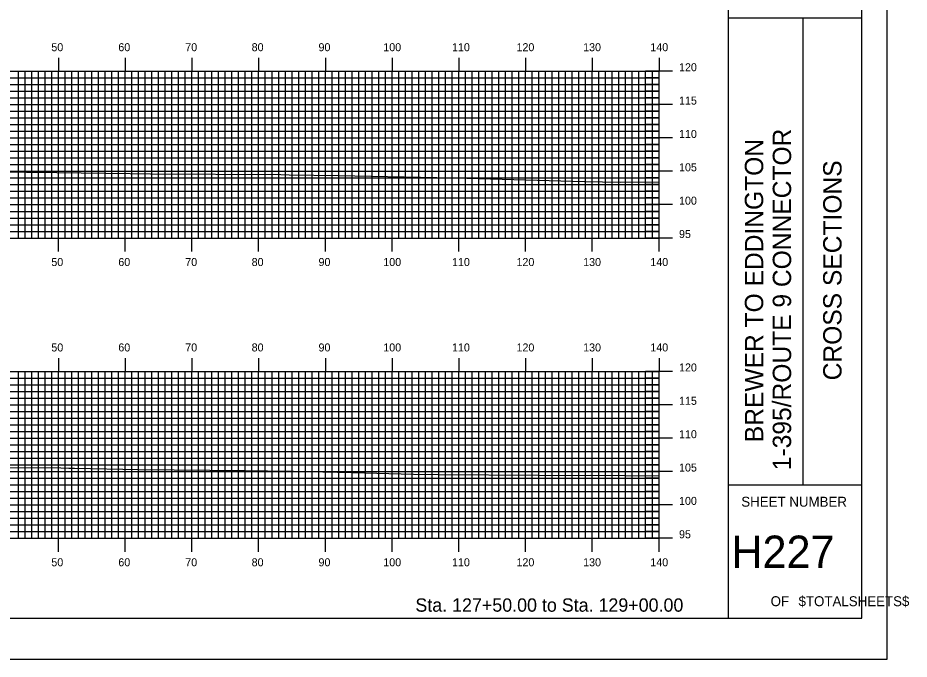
# Model space of a CAD drawing. Extents: x 1773596 to 1773940, y 442591 to 442811.
# Drawn here: x 1773806.1 to 1773939.6, y 442590.5 to 442686.7 of the extents above; entities that cross this region are included whole.
import ezdxf

# ---------------------------------------------------------------- set-up
doc = ezdxf.new("R2010")
doc.units = 0
for name, color, linetype in [('BORDER', 7, 'Continuous'), ('H_V ANNOTATION', 7, 'Continuous'), ('MAJOR', 7, 'Continuous'), ('MINOR', 7, 'Continuous'), ('PLOT BOUNDARY', 7, 'Continuous'), ('S_Roadway_Centerline', 7, 'Continuous')]:
    doc.layers.add(name, color=color, linetype=linetype)

msp = doc.modelspace()

# ---------------------------------------------------------------- linework, layer by layer
at = {"layer": 'BORDER'}
for p, q in [((1773912.55, 442596.67), (1773912.55, 442806.67)), ((1773912.55, 442686.67), (1773932.55, 442686.67)), ((1773923.73, 442616.67), (1773923.73, 442686.67)), ((1773912.55, 442616.67), (1773932.55, 442616.67))]:
    msp.add_line(p, q, dxfattribs=at)
msp.add_lwpolyline([(1773612.55, 442596.67), (1773932.55, 442596.67), (1773932.55, 442806.67), (1773612.55, 442806.67)], close=True, dxfattribs=at)
at = {"layer": 'MAJOR'}
for p, q in [((1773812.15, 442680.67), (1773812.15, 442678.67)), ((1773822.15, 442680.67), (1773822.15, 442678.67)), ((1773832.15, 442680.67), (1773832.15, 442678.67)), ((1773842.15, 442680.67), (1773842.15, 442678.67)), ((1773852.15, 442680.67), (1773852.15, 442678.67)), ((1773862.15, 442680.67), (1773862.15, 442678.67)), ((1773872.15, 442680.67), (1773872.15, 442678.67)), ((1773882.15, 442680.67), (1773882.15, 442678.67)), ((1773892.15, 442680.67), (1773892.15, 442678.67)), ((1773902.15, 442680.67), (1773902.15, 442678.67)), ((1773622.15, 442678.67), (1773902.15, 442678.67)), ((1773622.15, 442678.67), (1773902.15, 442678.67)), ((1773812.15, 442653.67), (1773812.15, 442678.67)), ((1773822.15, 442653.67), (1773822.15, 442678.67)), ((1773832.15, 442653.67), (1773832.15, 442678.67)), ((1773842.15, 442653.67), (1773842.15, 442678.67)), ((1773852.15, 442653.67), (1773852.15, 442678.67)), ((1773862.15, 442653.67), (1773862.15, 442678.67)), ((1773872.15, 442653.67), (1773872.15, 442678.67)), ((1773882.15, 442653.67), (1773882.15, 442678.67)), ((1773892.15, 442653.67), (1773892.15, 442678.67)), ((1773904.15, 442678.67), (1773900.14, 442678.67)), ((1773902.15, 442653.67), (1773902.15, 442678.67)), ((1773902.15, 442653.67), (1773902.15, 442678.67)), ((1773622.15, 442673.67), (1773902.15, 442673.67)), ((1773904.15, 442673.67), (1773900.14, 442673.67)), ((1773622.15, 442668.67), (1773902.15, 442668.67)), ((1773904.15, 442668.67), (1773900.14, 442668.67)), ((1773622.15, 442663.67), (1773902.15, 442663.67)), ((1773904.15, 442663.67), (1773900.14, 442663.67)), ((1773622.15, 442658.67), (1773902.15, 442658.67)), ((1773904.15, 442658.67), (1773900.14, 442658.67)), ((1773622.15, 442653.67), (1773902.15, 442653.67)), ((1773622.15, 442653.67), (1773902.15, 442653.67)), ((1773812.15, 442651.66), (1773812.15, 442653.67)), ((1773822.15, 442651.66), (1773822.15, 442653.67)), ((1773832.15, 442651.66), (1773832.15, 442653.67)), ((1773842.15, 442651.66), (1773842.15, 442653.67)), ((1773852.15, 442651.66), (1773852.15, 442653.67)), ((1773862.15, 442651.66), (1773862.15, 442653.67)), ((1773872.15, 442651.66), (1773872.15, 442653.67)), ((1773882.15, 442651.66), (1773882.15, 442653.67)), ((1773892.15, 442651.66), (1773892.15, 442653.67)), ((1773904.15, 442653.67), (1773900.14, 442653.67)), ((1773902.15, 442651.66), (1773902.15, 442653.67)), ((1773812.15, 442635.67), (1773812.15, 442633.67)), ((1773822.15, 442635.67), (1773822.15, 442633.67)), ((1773832.15, 442635.67), (1773832.15, 442633.67)), ((1773842.15, 442635.67), (1773842.15, 442633.67)), ((1773852.15, 442635.67), (1773852.15, 442633.67)), ((1773862.15, 442635.67), (1773862.15, 442633.67)), ((1773872.15, 442635.67), (1773872.15, 442633.67)), ((1773882.15, 442635.67), (1773882.15, 442633.67)), ((1773892.15, 442635.67), (1773892.15, 442633.67)), ((1773902.15, 442635.67), (1773902.15, 442633.67)), ((1773622.15, 442633.67), (1773902.15, 442633.67)), ((1773622.15, 442633.67), (1773902.15, 442633.67)), ((1773812.15, 442608.67), (1773812.15, 442633.67)), ((1773822.15, 442608.67), (1773822.15, 442633.67)), ((1773832.15, 442608.67), (1773832.15, 442633.67)), ((1773842.15, 442608.67), (1773842.15, 442633.67)), ((1773852.15, 442608.67), (1773852.15, 442633.67)), ((1773862.15, 442608.67), (1773862.15, 442633.67)), ((1773872.15, 442608.67), (1773872.15, 442633.67)), ((1773882.15, 442608.67), (1773882.15, 442633.67)), ((1773892.15, 442608.67), (1773892.15, 442633.67)), ((1773904.15, 442633.67), (1773900.14, 442633.67)), ((1773902.15, 442608.67), (1773902.15, 442633.67)), ((1773902.15, 442608.67), (1773902.15, 442633.67)), ((1773622.15, 442628.67), (1773902.15, 442628.67)), ((1773904.15, 442628.67), (1773900.14, 442628.67)), ((1773622.15, 442623.67), (1773902.15, 442623.67)), ((1773904.15, 442623.67), (1773900.14, 442623.67)), ((1773622.15, 442618.67), (1773902.15, 442618.67)), ((1773904.15, 442618.67), (1773900.14, 442618.67)), ((1773622.15, 442613.67), (1773902.15, 442613.67)), ((1773904.15, 442613.67), (1773900.14, 442613.67)), ((1773622.15, 442608.67), (1773902.15, 442608.67)), ((1773622.15, 442608.67), (1773902.15, 442608.67)), ((1773812.15, 442606.66), (1773812.15, 442608.67)), ((1773822.15, 442606.66), (1773822.15, 442608.67)), ((1773832.15, 442606.66), (1773832.15, 442608.67)), ((1773842.15, 442606.66), (1773842.15, 442608.67)), ((1773852.15, 442606.66), (1773852.15, 442608.67)), ((1773862.15, 442606.66), (1773862.15, 442608.67)), ((1773872.15, 442606.66), (1773872.15, 442608.67)), ((1773882.15, 442606.66), (1773882.15, 442608.67)), ((1773892.15, 442606.66), (1773892.15, 442608.67)), ((1773904.15, 442608.67), (1773900.14, 442608.67)), ((1773902.15, 442606.66), (1773902.15, 442608.67))]:
    msp.add_line(p, q, dxfattribs=at)
at = {"layer": 'MINOR'}
for p, q in [((1773806.15, 442653.67), (1773806.15, 442678.67)), ((1773807.15, 442653.67), (1773807.15, 442678.67)), ((1773808.15, 442653.67), (1773808.15, 442678.67)), ((1773809.15, 442653.67), (1773809.15, 442678.67)), ((1773810.15, 442653.67), (1773810.15, 442678.67)), ((1773811.15, 442653.67), (1773811.15, 442678.67)), ((1773813.15, 442653.67), (1773813.15, 442678.67)), ((1773814.15, 442653.67), (1773814.15, 442678.67)), ((1773815.15, 442653.67), (1773815.15, 442678.67)), ((1773816.15, 442653.67), (1773816.15, 442678.67)), ((1773817.15, 442653.67), (1773817.15, 442678.67)), ((1773818.15, 442653.67), (1773818.15, 442678.67)), ((1773819.15, 442653.67), (1773819.15, 442678.67)), ((1773820.15, 442653.67), (1773820.15, 442678.67)), ((1773821.15, 442653.67), (1773821.15, 442678.67)), ((1773823.15, 442653.67), (1773823.15, 442678.67)), ((1773824.15, 442653.67), (1773824.15, 442678.67)), ((1773825.15, 442653.67), (1773825.15, 442678.67)), ((1773826.15, 442653.67), (1773826.15, 442678.67)), ((1773827.15, 442653.67), (1773827.15, 442678.67)), ((1773828.15, 442653.67), (1773828.15, 442678.67)), ((1773829.15, 442653.67), (1773829.15, 442678.67)), ((1773830.15, 442653.67), (1773830.15, 442678.67)), ((1773831.15, 442653.67), (1773831.15, 442678.67)), ((1773833.15, 442653.67), (1773833.15, 442678.67)), ((1773834.15, 442653.67), (1773834.15, 442678.67)), ((1773835.15, 442653.67), (1773835.15, 442678.67)), ((1773836.15, 442653.67), (1773836.15, 442678.67)), ((1773837.15, 442653.67), (1773837.15, 442678.67)), ((1773838.15, 442653.67), (1773838.15, 442678.67)), ((1773839.15, 442653.67), (1773839.15, 442678.67)), ((1773840.15, 442653.67), (1773840.15, 442678.67)), ((1773841.15, 442653.67), (1773841.15, 442678.67)), ((1773843.15, 442653.67), (1773843.15, 442678.67)), ((1773844.15, 442653.67), (1773844.15, 442678.67)), ((1773845.15, 442653.67), (1773845.15, 442678.67)), ((1773846.15, 442653.67), (1773846.15, 442678.67)), ((1773847.15, 442653.67), (1773847.15, 442678.67)), ((1773848.15, 442653.67), (1773848.15, 442678.67)), ((1773849.15, 442653.67), (1773849.15, 442678.67)), ((1773850.15, 442653.67), (1773850.15, 442678.67)), ((1773851.15, 442653.67), (1773851.15, 442678.67)), ((1773853.15, 442653.67), (1773853.15, 442678.67)), ((1773854.15, 442653.67), (1773854.15, 442678.67)), ((1773855.15, 442653.67), (1773855.15, 442678.67)), ((1773856.15, 442653.67), (1773856.15, 442678.67)), ((1773857.15, 442653.67), (1773857.15, 442678.67)), ((1773858.15, 442653.67), (1773858.15, 442678.67)), ((1773859.15, 442653.67), (1773859.15, 442678.67)), ((1773860.15, 442653.67), (1773860.15, 442678.67)), ((1773861.15, 442653.67), (1773861.15, 442678.67)), ((1773863.15, 442653.67), (1773863.15, 442678.67)), ((1773864.15, 442653.67), (1773864.15, 442678.67)), ((1773865.15, 442653.67), (1773865.15, 442678.67)), ((1773866.15, 442653.67), (1773866.15, 442678.67)), ((1773867.15, 442653.67), (1773867.15, 442678.67)), ((1773868.15, 442653.67), (1773868.15, 442678.67)), ((1773869.15, 442653.67), (1773869.15, 442678.67)), ((1773870.15, 442653.67), (1773870.15, 442678.67)), ((1773871.15, 442653.67), (1773871.15, 442678.67)), ((1773873.15, 442653.67), (1773873.15, 442678.67)), ((1773874.15, 442653.67), (1773874.15, 442678.67)), ((1773875.15, 442653.67), (1773875.15, 442678.67)), ((1773876.15, 442653.67), (1773876.15, 442678.67)), ((1773877.15, 442653.67), (1773877.15, 442678.67)), ((1773878.15, 442653.67), (1773878.15, 442678.67)), ((1773879.15, 442653.67), (1773879.15, 442678.67)), ((1773880.15, 442653.67), (1773880.15, 442678.67)), ((1773881.15, 442653.67), (1773881.15, 442678.67)), ((1773883.15, 442653.67), (1773883.15, 442678.67)), ((1773884.15, 442653.67), (1773884.15, 442678.67)), ((1773885.15, 442653.67), (1773885.15, 442678.67)), ((1773886.15, 442653.67), (1773886.15, 442678.67)), ((1773887.15, 442653.67), (1773887.15, 442678.67)), ((1773888.15, 442653.67), (1773888.15, 442678.67)), ((1773889.15, 442653.67), (1773889.15, 442678.67)), ((1773890.15, 442653.67), (1773890.15, 442678.67)), ((1773891.15, 442653.67), (1773891.15, 442678.67)), ((1773893.15, 442653.67), (1773893.15, 442678.67)), ((1773894.15, 442653.67), (1773894.15, 442678.67)), ((1773895.15, 442653.67), (1773895.15, 442678.67)), ((1773896.15, 442653.67), (1773896.15, 442678.67)), ((1773897.15, 442653.67), (1773897.15, 442678.67)), ((1773898.15, 442653.67), (1773898.15, 442678.67)), ((1773899.15, 442653.67), (1773899.15, 442678.67)), ((1773900.15, 442653.67), (1773900.15, 442678.67)), ((1773901.15, 442653.67), (1773901.15, 442678.67)), ((1773622.15, 442677.67), (1773902.15, 442677.67)), ((1773902.15, 442677.67), (1773900.14, 442677.67)), ((1773622.15, 442676.67), (1773902.15, 442676.67)), ((1773622.15, 442675.67), (1773902.15, 442675.67)), ((1773902.15, 442676.67), (1773900.14, 442676.67)), ((1773902.15, 442675.67), (1773900.14, 442675.67)), ((1773622.15, 442674.67), (1773902.15, 442674.67)), ((1773902.15, 442674.67), (1773900.14, 442674.67)), ((1773622.15, 442672.67), (1773902.15, 442672.67)), ((1773622.15, 442671.67), (1773902.15, 442671.67)), ((1773902.15, 442672.67), (1773900.14, 442672.67)), ((1773902.15, 442671.67), (1773900.14, 442671.67)), ((1773622.15, 442670.67), (1773902.15, 442670.67)), ((1773902.15, 442670.67), (1773900.14, 442670.67)), ((1773622.15, 442669.67), (1773902.15, 442669.67)), ((1773902.15, 442669.67), (1773900.14, 442669.67)), ((1773622.15, 442667.67), (1773902.15, 442667.67)), ((1773902.15, 442667.67), (1773900.14, 442667.67)), ((1773622.15, 442666.67), (1773902.15, 442666.67)), ((1773902.15, 442666.67), (1773900.14, 442666.67)), ((1773622.15, 442665.67), (1773902.15, 442665.67)), ((1773902.15, 442665.67), (1773900.14, 442665.67)), ((1773622.15, 442664.67), (1773902.15, 442664.67)), ((1773902.15, 442664.67), (1773900.14, 442664.67)), ((1773622.15, 442662.67), (1773902.15, 442662.67)), ((1773902.15, 442662.67), (1773900.14, 442662.67)), ((1773622.15, 442661.67), (1773902.15, 442661.67)), ((1773902.15, 442661.67), (1773900.14, 442661.67)), ((1773622.15, 442660.67), (1773902.15, 442660.67)), ((1773622.15, 442659.67), (1773902.15, 442659.67)), ((1773902.15, 442660.67), (1773900.14, 442660.67)), ((1773902.15, 442659.67), (1773900.14, 442659.67)), ((1773622.15, 442657.67), (1773902.15, 442657.67)), ((1773902.15, 442657.67), (1773900.14, 442657.67)), ((1773622.15, 442656.67), (1773902.15, 442656.67)), ((1773622.15, 442655.67), (1773902.15, 442655.67)), ((1773902.15, 442656.67), (1773900.14, 442656.67)), ((1773902.15, 442655.67), (1773900.14, 442655.67)), ((1773622.15, 442654.67), (1773902.15, 442654.67)), ((1773902.15, 442654.67), (1773900.14, 442654.67)), ((1773806.15, 442608.67), (1773806.15, 442633.67)), ((1773807.15, 442608.67), (1773807.15, 442633.67)), ((1773808.15, 442608.67), (1773808.15, 442633.67)), ((1773809.15, 442608.67), (1773809.15, 442633.67)), ((1773810.15, 442608.67), (1773810.15, 442633.67)), ((1773811.15, 442608.67), (1773811.15, 442633.67)), ((1773813.15, 442608.67), (1773813.15, 442633.67)), ((1773814.15, 442608.67), (1773814.15, 442633.67)), ((1773815.15, 442608.67), (1773815.15, 442633.67)), ((1773816.15, 442608.67), (1773816.15, 442633.67)), ((1773817.15, 442608.67), (1773817.15, 442633.67)), ((1773818.15, 442608.67), (1773818.15, 442633.67)), ((1773819.15, 442608.67), (1773819.15, 442633.67)), ((1773820.15, 442608.67), (1773820.15, 442633.67)), ((1773821.15, 442608.67), (1773821.15, 442633.67)), ((1773823.15, 442608.67), (1773823.15, 442633.67)), ((1773824.15, 442608.67), (1773824.15, 442633.67)), ((1773825.15, 442608.67), (1773825.15, 442633.67)), ((1773826.15, 442608.67), (1773826.15, 442633.67)), ((1773827.15, 442608.67), (1773827.15, 442633.67)), ((1773828.15, 442608.67), (1773828.15, 442633.67)), ((1773829.15, 442608.67), (1773829.15, 442633.67)), ((1773830.15, 442608.67), (1773830.15, 442633.67)), ((1773831.15, 442608.67), (1773831.15, 442633.67)), ((1773833.15, 442608.67), (1773833.15, 442633.67)), ((1773834.15, 442608.67), (1773834.15, 442633.67)), ((1773835.15, 442608.67), (1773835.15, 442633.67)), ((1773836.15, 442608.67), (1773836.15, 442633.67)), ((1773837.15, 442608.67), (1773837.15, 442633.67)), ((1773838.15, 442608.67), (1773838.15, 442633.67)), ((1773839.15, 442608.67), (1773839.15, 442633.67)), ((1773840.15, 442608.67), (1773840.15, 442633.67)), ((1773841.15, 442608.67), (1773841.15, 442633.67)), ((1773843.15, 442608.67), (1773843.15, 442633.67)), ((1773844.15, 442608.67), (1773844.15, 442633.67)), ((1773845.15, 442608.67), (1773845.15, 442633.67)), ((1773846.15, 442608.67), (1773846.15, 442633.67)), ((1773847.15, 442608.67), (1773847.15, 442633.67)), ((1773848.15, 442608.67), (1773848.15, 442633.67)), ((1773849.15, 442608.67), (1773849.15, 442633.67)), ((1773850.15, 442608.67), (1773850.15, 442633.67)), ((1773851.15, 442608.67), (1773851.15, 442633.67)), ((1773853.15, 442608.67), (1773853.15, 442633.67)), ((1773854.15, 442608.67), (1773854.15, 442633.67)), ((1773855.15, 442608.67), (1773855.15, 442633.67)), ((1773856.15, 442608.67), (1773856.15, 442633.67)), ((1773857.15, 442608.67), (1773857.15, 442633.67)), ((1773858.15, 442608.67), (1773858.15, 442633.67)), ((1773859.15, 442608.67), (1773859.15, 442633.67)), ((1773860.15, 442608.67), (1773860.15, 442633.67)), ((1773861.15, 442608.67), (1773861.15, 442633.67)), ((1773863.15, 442608.67), (1773863.15, 442633.67)), ((1773864.15, 442608.67), (1773864.15, 442633.67)), ((1773865.15, 442608.67), (1773865.15, 442633.67)), ((1773866.15, 442608.67), (1773866.15, 442633.67)), ((1773867.15, 442608.67), (1773867.15, 442633.67)), ((1773868.15, 442608.67), (1773868.15, 442633.67)), ((1773869.15, 442608.67), (1773869.15, 442633.67)), ((1773870.15, 442608.67), (1773870.15, 442633.67)), ((1773871.15, 442608.67), (1773871.15, 442633.67)), ((1773873.15, 442608.67), (1773873.15, 442633.67)), ((1773874.15, 442608.67), (1773874.15, 442633.67)), ((1773875.15, 442608.67), (1773875.15, 442633.67)), ((1773876.15, 442608.67), (1773876.15, 442633.67)), ((1773877.15, 442608.67), (1773877.15, 442633.67)), ((1773878.15, 442608.67), (1773878.15, 442633.67)), ((1773879.15, 442608.67), (1773879.15, 442633.67)), ((1773880.15, 442608.67), (1773880.15, 442633.67)), ((1773881.15, 442608.67), (1773881.15, 442633.67)), ((1773883.15, 442608.67), (1773883.15, 442633.67)), ((1773884.15, 442608.67), (1773884.15, 442633.67)), ((1773885.15, 442608.67), (1773885.15, 442633.67)), ((1773886.15, 442608.67), (1773886.15, 442633.67)), ((1773887.15, 442608.67), (1773887.15, 442633.67)), ((1773888.15, 442608.67), (1773888.15, 442633.67)), ((1773889.15, 442608.67), (1773889.15, 442633.67)), ((1773890.15, 442608.67), (1773890.15, 442633.67)), ((1773891.15, 442608.67), (1773891.15, 442633.67)), ((1773893.15, 442608.67), (1773893.15, 442633.67)), ((1773894.15, 442608.67), (1773894.15, 442633.67)), ((1773895.15, 442608.67), (1773895.15, 442633.67)), ((1773896.15, 442608.67), (1773896.15, 442633.67)), ((1773897.15, 442608.67), (1773897.15, 442633.67)), ((1773898.15, 442608.67), (1773898.15, 442633.67)), ((1773899.15, 442608.67), (1773899.15, 442633.67)), ((1773900.15, 442608.67), (1773900.15, 442633.67)), ((1773901.15, 442608.67), (1773901.15, 442633.67)), ((1773622.15, 442632.67), (1773902.15, 442632.67)), ((1773622.15, 442631.67), (1773902.15, 442631.67)), ((1773902.15, 442632.67), (1773900.14, 442632.67)), ((1773902.15, 442631.67), (1773900.14, 442631.67)), ((1773622.15, 442630.67), (1773902.15, 442630.67)), ((1773902.15, 442630.67), (1773900.14, 442630.67)), ((1773622.15, 442629.67), (1773902.15, 442629.67)), ((1773902.15, 442629.67), (1773900.14, 442629.67)), ((1773622.15, 442627.67), (1773902.15, 442627.67)), ((1773902.15, 442627.67), (1773900.14, 442627.67)), ((1773622.15, 442626.67), (1773902.15, 442626.67)), ((1773902.15, 442626.67), (1773900.14, 442626.67)), ((1773622.15, 442625.67), (1773902.15, 442625.67)), ((1773902.15, 442625.67), (1773900.14, 442625.67)), ((1773622.15, 442624.67), (1773902.15, 442624.67)), ((1773902.15, 442624.67), (1773900.14, 442624.67)), ((1773622.15, 442622.67), (1773902.15, 442622.67)), ((1773902.15, 442622.67), (1773900.14, 442622.67)), ((1773622.15, 442621.67), (1773902.15, 442621.67)), ((1773902.15, 442621.67), (1773900.14, 442621.67)), ((1773622.15, 442620.67), (1773902.15, 442620.67)), ((1773622.15, 442619.67), (1773902.15, 442619.67)), ((1773902.15, 442620.67), (1773900.14, 442620.67)), ((1773902.15, 442619.67), (1773900.14, 442619.67)), ((1773622.15, 442617.67), (1773902.15, 442617.67)), ((1773902.15, 442617.67), (1773900.14, 442617.67)), ((1773622.15, 442616.67), (1773902.15, 442616.67)), ((1773622.15, 442615.67), (1773902.15, 442615.67)), ((1773902.15, 442616.67), (1773900.14, 442616.67)), ((1773902.15, 442615.67), (1773900.14, 442615.67)), ((1773622.15, 442614.67), (1773902.15, 442614.67)), ((1773902.15, 442614.67), (1773900.14, 442614.67)), ((1773622.15, 442612.67), (1773902.15, 442612.67)), ((1773622.15, 442611.67), (1773902.15, 442611.67)), ((1773902.15, 442612.67), (1773900.14, 442612.67)), ((1773902.15, 442611.67), (1773900.14, 442611.67)), ((1773622.15, 442610.67), (1773902.15, 442610.67)), ((1773902.15, 442610.67), (1773900.14, 442610.67)), ((1773622.15, 442609.67), (1773902.15, 442609.67)), ((1773902.15, 442609.67), (1773900.14, 442609.67))]:
    msp.add_line(p, q, dxfattribs=at)
at = {"layer": 'PLOT BOUNDARY'}
msp.add_lwpolyline([(1773596.36, 442590.55), (1773936.36, 442590.55), (1773936.36, 442810.55), (1773596.36, 442810.55)], close=True, dxfattribs=at)
at = {"layer": 'S_Roadway_Centerline'}
for points in [[(1773802.76, 442663.6), (1773811.88, 442663.47), (1773822.89, 442663.33), (1773825.93, 442663.3), (1773845.45, 442663.17), (1773846.7, 442663.16), (1773854.13, 442663.02), (1773868.87, 442662.72), (1773870.13, 442662.71), (1773871.59, 442662.71), (1773891, 442662.12), (1773896.38, 442662.04), (1773902.15, 442662.08)], [(1773802.63, 442619.28), (1773812.5, 442619.22), (1773813.7, 442619.2), (1773814.56, 442619.19), (1773824.19, 442619), (1773840.12, 442618.82), (1773843.47, 442618.76), (1773847.38, 442618.73), (1773856.15, 442618.55), (1773865.34, 442618.3), (1773869.13, 442618.22), (1773884.07, 442618.13), (1773891.04, 442618.09), (1773891.9, 442618.14), (1773902.15, 442618.01)]]:
    msp.add_lwpolyline(points, dxfattribs=at)

# ---------------------------------------------------------------- texts
at = {"layer": 'BORDER'}
for s, p in [('1-395/ROUTE 9 CONNECTOR', (1773921.95, 442618.87)), ('BREWER TO EDDINGTON', (1773917.77, 442623.07)), ('CROSS SECTIONS', (1773929.51, 442632.34))]:
    msp.add_text(s, height=2.7557, rotation=90, dxfattribs=at).set_placement(p)
for s, height, p in [('SHEET NUMBER', 1.4905, (1773914.48, 442613.4)), ('H227', 4.839, (1773912.99, 442604.23)), ('OF', 1.491, (1773918.88, 442598.49)), ('$TOTALSHEETS$', 1.4905, (1773923.06, 442598.49))]:
    msp.add_text(s, height=height, dxfattribs=at).set_placement(p)
at = {"layer": 'H_V ANNOTATION'}
for s, height, p in [('50', 1.2, (1773811.08, 442681.67)), ('60', 1.2, (1773821.12, 442681.67)), ('70', 1.2, (1773831.15, 442681.67)), ('80', 1.2, (1773841.1, 442681.67)), ('90', 1.2, (1773851.12, 442681.67)), ('100', 1.2, (1773860.83, 442681.67)), ('110', 1.2, (1773871.13, 442681.67)), ('120', 1.2, (1773880.79, 442681.67)), ('130', 1.2, (1773890.78, 442681.67)), ('140', 1.2, (1773900.85, 442681.67)), ('120', 1.2, (1773905.15, 442678.67)), ('115', 1.2, (1773905.15, 442673.67)), ('110', 1.2, (1773905.15, 442668.67)), ('105', 1.2, (1773905.15, 442663.67)), ('100', 1.2, (1773905.15, 442658.67)), ('95', 1.2, (1773905.15, 442653.67)), ('50', 1.2, (1773811.08, 442649.47)), ('60', 1.2, (1773821.12, 442649.47)), ('70', 1.2, (1773831.15, 442649.47)), ('80', 1.2, (1773841.1, 442649.47)), ('90', 1.2, (1773851.12, 442649.47)), ('100', 1.2, (1773860.83, 442649.47)), ('110', 1.2, (1773871.13, 442649.47)), ('120', 1.2, (1773880.79, 442649.47)), ('130', 1.2, (1773890.78, 442649.47)), ('140', 1.2, (1773900.85, 442649.47)), ('50', 1.2, (1773811.08, 442636.67)), ('60', 1.2, (1773821.12, 442636.67)), ('70', 1.2, (1773831.15, 442636.67)), ('80', 1.2, (1773841.1, 442636.67)), ('90', 1.2, (1773851.12, 442636.67)), ('100', 1.2, (1773860.83, 442636.67)), ('110', 1.2, (1773871.13, 442636.67)), ('120', 1.2, (1773880.79, 442636.67)), ('130', 1.2, (1773890.78, 442636.67)), ('140', 1.2, (1773900.85, 442636.67)), ('120', 1.2, (1773905.15, 442633.67)), ('115', 1.2, (1773905.15, 442628.67)), ('110', 1.2, (1773905.15, 442623.67)), ('105', 1.2, (1773905.15, 442618.67)), ('100', 1.2, (1773905.15, 442613.67)), ('95', 1.2, (1773905.15, 442608.67)), ('50', 1.2, (1773811.08, 442604.47)), ('60', 1.2, (1773821.12, 442604.47)), ('70', 1.2, (1773831.15, 442604.47)), ('80', 1.2, (1773841.1, 442604.47)), ('90', 1.2, (1773851.12, 442604.47)), ('100', 1.2, (1773860.83, 442604.47)), ('110', 1.2, (1773871.13, 442604.47)), ('120', 1.2, (1773880.79, 442604.47)), ('130', 1.2, (1773890.78, 442604.47)), ('140', 1.2, (1773900.85, 442604.47)), ('Sta. 127+50.00 to Sta. 129+00.00', 2.0004, (1773865.64, 442597.66))]:
    msp.add_text(s, height=height, dxfattribs=at).set_placement(p)

doc.saveas('drawing.dxf')
